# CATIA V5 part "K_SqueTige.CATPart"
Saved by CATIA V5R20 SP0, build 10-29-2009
Part number: Squelette_tige
Publications: "Axe_tige", "Point_centre_écrou", "Plan_tige"
Bounding box of the stored display mesh (mm): x -351 to -311, y -92.303 to -92.303, z 0 to 0
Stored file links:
  G:\Khaled_CFAO_2011\ST2M\ST2M_GR2\jcoetard\Khaled\CAD_CATIA\K_SqueTige.CATPart
  G:\Khaled_CFAO_2011\ST2M\ST2M_GR2\jcoetard\Khaled\CAD_CATIA\K_Squelette.CATProduct
  G:\Khaled_CFAO_2011\ST2M\ST2M_GR2\jcoetard\jcoetard\Maquette_jcoetard\Squelette_ecrou.CATPart
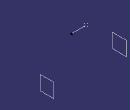
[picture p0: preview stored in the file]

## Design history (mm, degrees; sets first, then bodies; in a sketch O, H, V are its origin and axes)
Set1
  Plane1 "Plan_écrou": linked copy from another document
Set2 "Set géométrique"
  Point1 "Point_centre_écrou": type OnPlane, Support Plane1, H -92.303, V 0, Direction (0, 1, 0)
  Line1 "Axe_tige": type Normal, RefPoint Point1, RefSkin Plane1, Start 0, End 40
  Plane2 "Plan_tige": type Offset, RefPlane yz-plane, Offset -150
Body1 (main body)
